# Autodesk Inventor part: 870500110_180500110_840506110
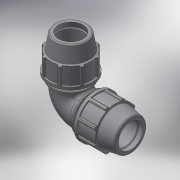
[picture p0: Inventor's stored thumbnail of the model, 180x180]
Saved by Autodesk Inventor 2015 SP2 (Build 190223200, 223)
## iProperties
Created: 2017-02
Part Number: 870500110_180500110_840506110
Material: Generic
Description: PLASSON 90° ELBOW 110-110
Document SubType Name: Modeling
Designer: KIM
Mass: 1923.39 g
Surface Area: 2516.77 cm^2
Volume: 1923.39 cm^3
Density: 1 g/cm^3
Appearance: Default
Author: KIM
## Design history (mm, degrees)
derived "87050.ipt"
feature "Solid1::87050.ipt"
tag "TaggingFeature1"
body "Solid1"
other parameters: "d4" = 24.5, "d5" = 73.5, "d7" = 181, "d9" = 42, "d11" = 11.76, "d13" = 120 deg, "d14" = 143, "d15" = 10 deg, "d16" = 166.52, "d18" = 5.5, "d19" = 35 deg, "d20" = 17.5 deg, "d21" = 168.33, "d23" = 0, "d25" = 360 deg, "d27" = 3.62, "d33" = 2.2, "d42" = 99.96, "d43" = 5.43, "d46" = 3.3, "d51" = 294, "d59" = 90 deg, "d63" = 196, "d64" = 99, "d67" = 135.75, "d68" = 21.168, "d70" = 90 deg, "d71" = 16.5, "d72" = 12.06667, "d73" = 0, "d75" = 90 deg, "d77" = 163.1896, "d78" = 7.056, "E_" = 181, "A_" = 294, "l_" = 196
